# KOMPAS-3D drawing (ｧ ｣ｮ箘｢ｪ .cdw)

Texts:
  ТМ-27А. КП.
  Заготовка
  Dance for life
  Текст на чертеже
  Размерные надписи
  Шероховатость
  Линия-выноска #1
  Линия-выноска #2
  Линия-выноска #3
  Отклонения формы и база
  Заголовок таблицы
  Ячейка таблицы
  Стрелка вида
  Обозначение изменения
  Фигурная скобка
  Номер узла
  Марка координационной оси
  VRCB
  Выносная надпись
  Обозначение узла
  Марка/позиционное обозначение с линией-выноской
  Марка/позиционное обозначение на линии
  Марка/позиционное обозначение без линии-выноски
  HB 160 20.
  Класс точности Т4, степень сложности С1, группа стали М2 по
  ГОСТ 7505-89.
  Неуказанные радиусы 2,5мм, штамповочные уклоны 7 .
  Величина смещения по плоскости разъёма штампа не более
  0,7мм, величина остаточного облоя не более 0,9мм.
  Глубина поверхностных дефектов не более половины припуска на
  обработку.
  Пескоструйная отчистка.
  - черновые технологические базы.
  Павлий
  Сталь 45 ГОСТ 1050-88
  НТУ "ХПИ"
  каф. АиТ
  ТМ-27А. КП.-
Dimensions and other numbers on the sheet: 7; 331,5; 231,4; 2,3; 2; 2,2; 2,7; 2,4; 73,1; 4; 1:1; 1; 0; 3; 5; 6; 8; 9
